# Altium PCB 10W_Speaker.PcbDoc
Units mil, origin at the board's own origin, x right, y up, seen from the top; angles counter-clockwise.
Board outline 4298.07 x 4067.91 mil, 4 copper layers (Top Layer, Internal Plane 2, Internal Plane 1, Bottom Layer), stack 30.634 mil thick; 46 components, 34 nets, 134 pads, 44 vias.
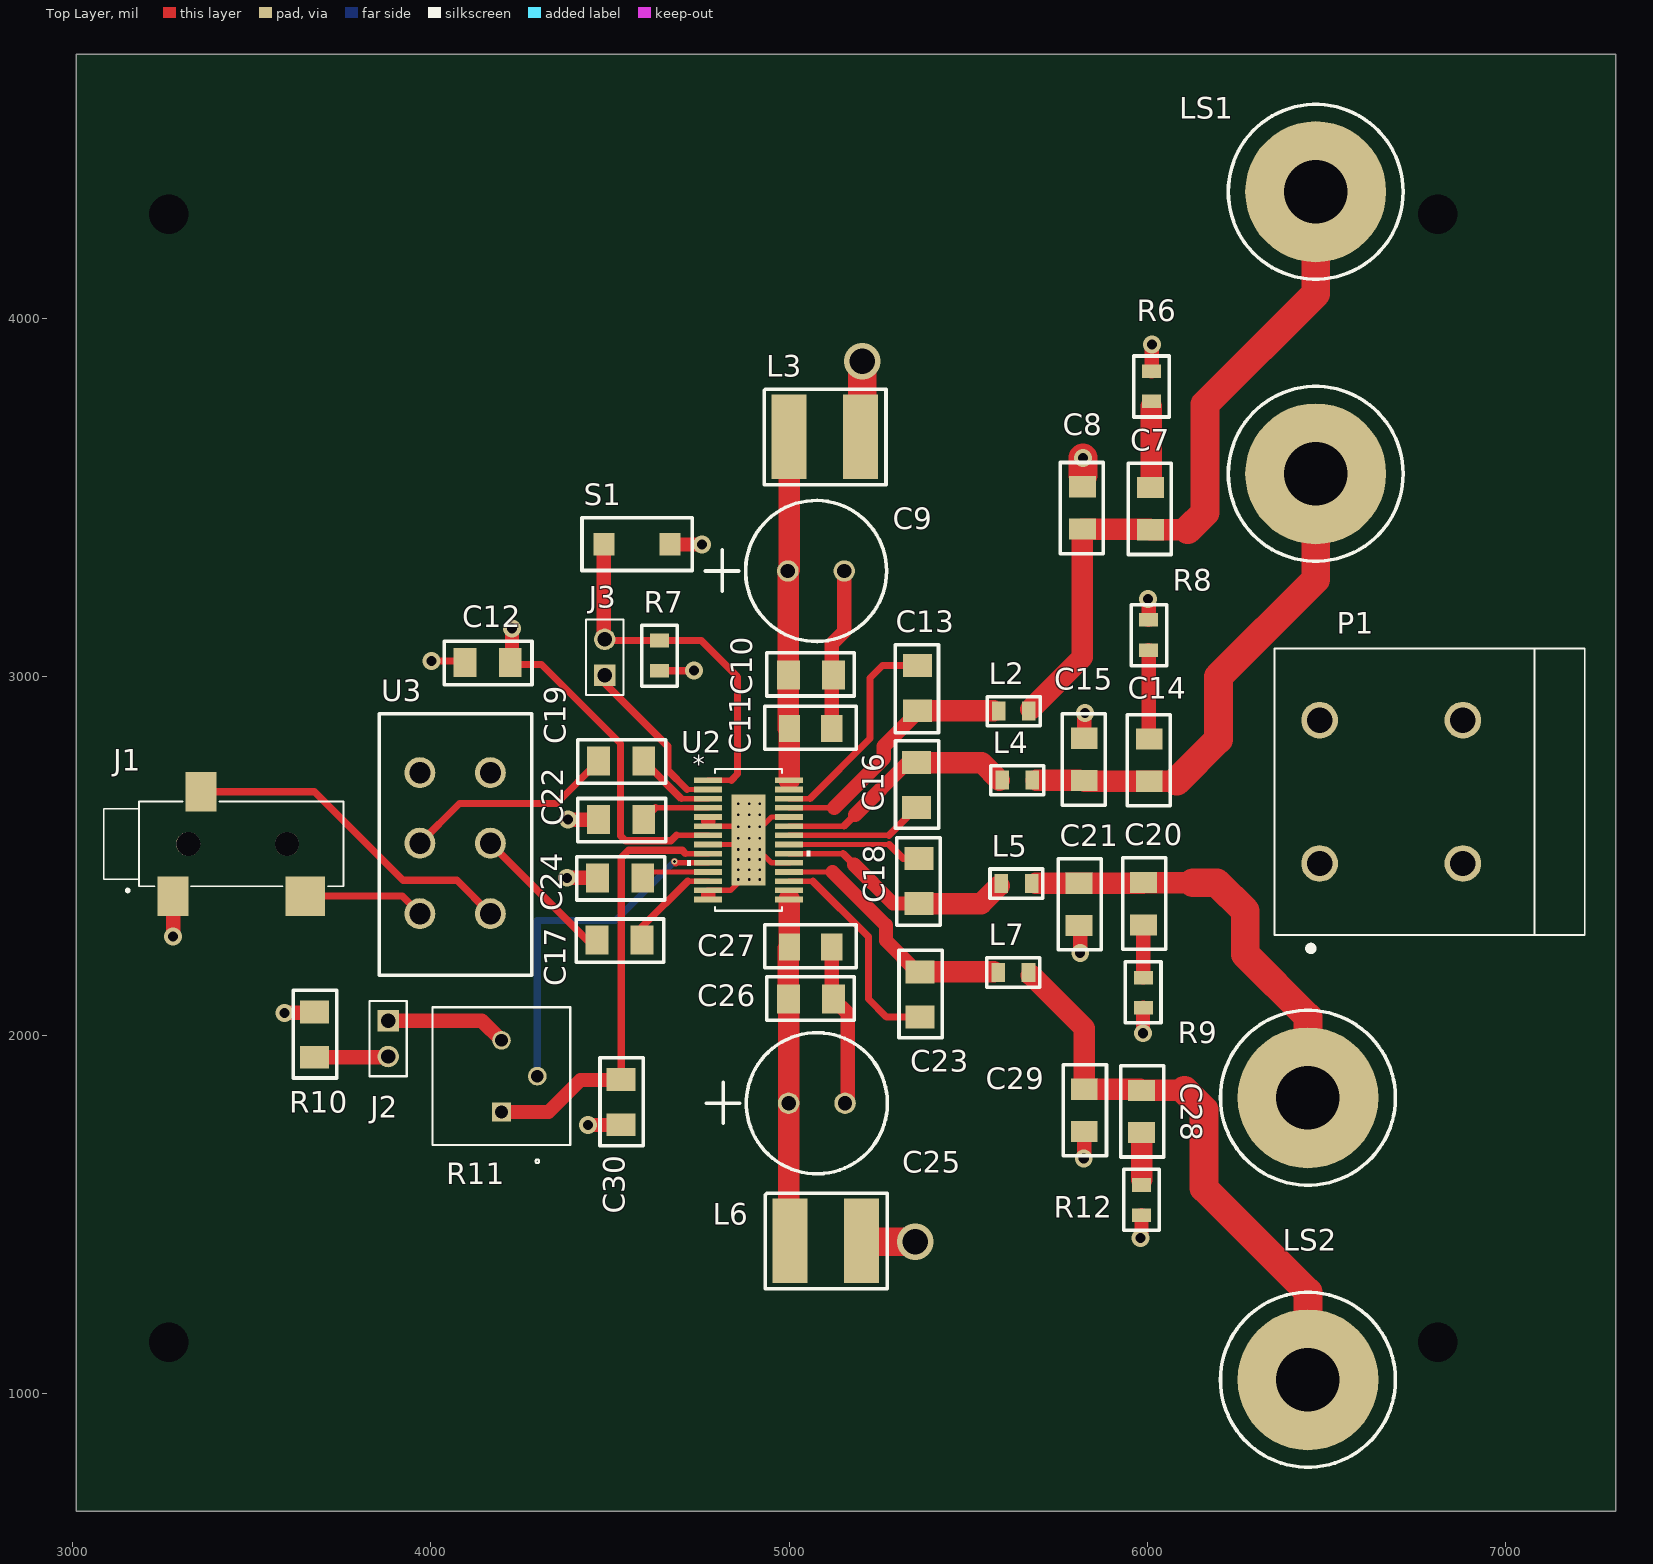
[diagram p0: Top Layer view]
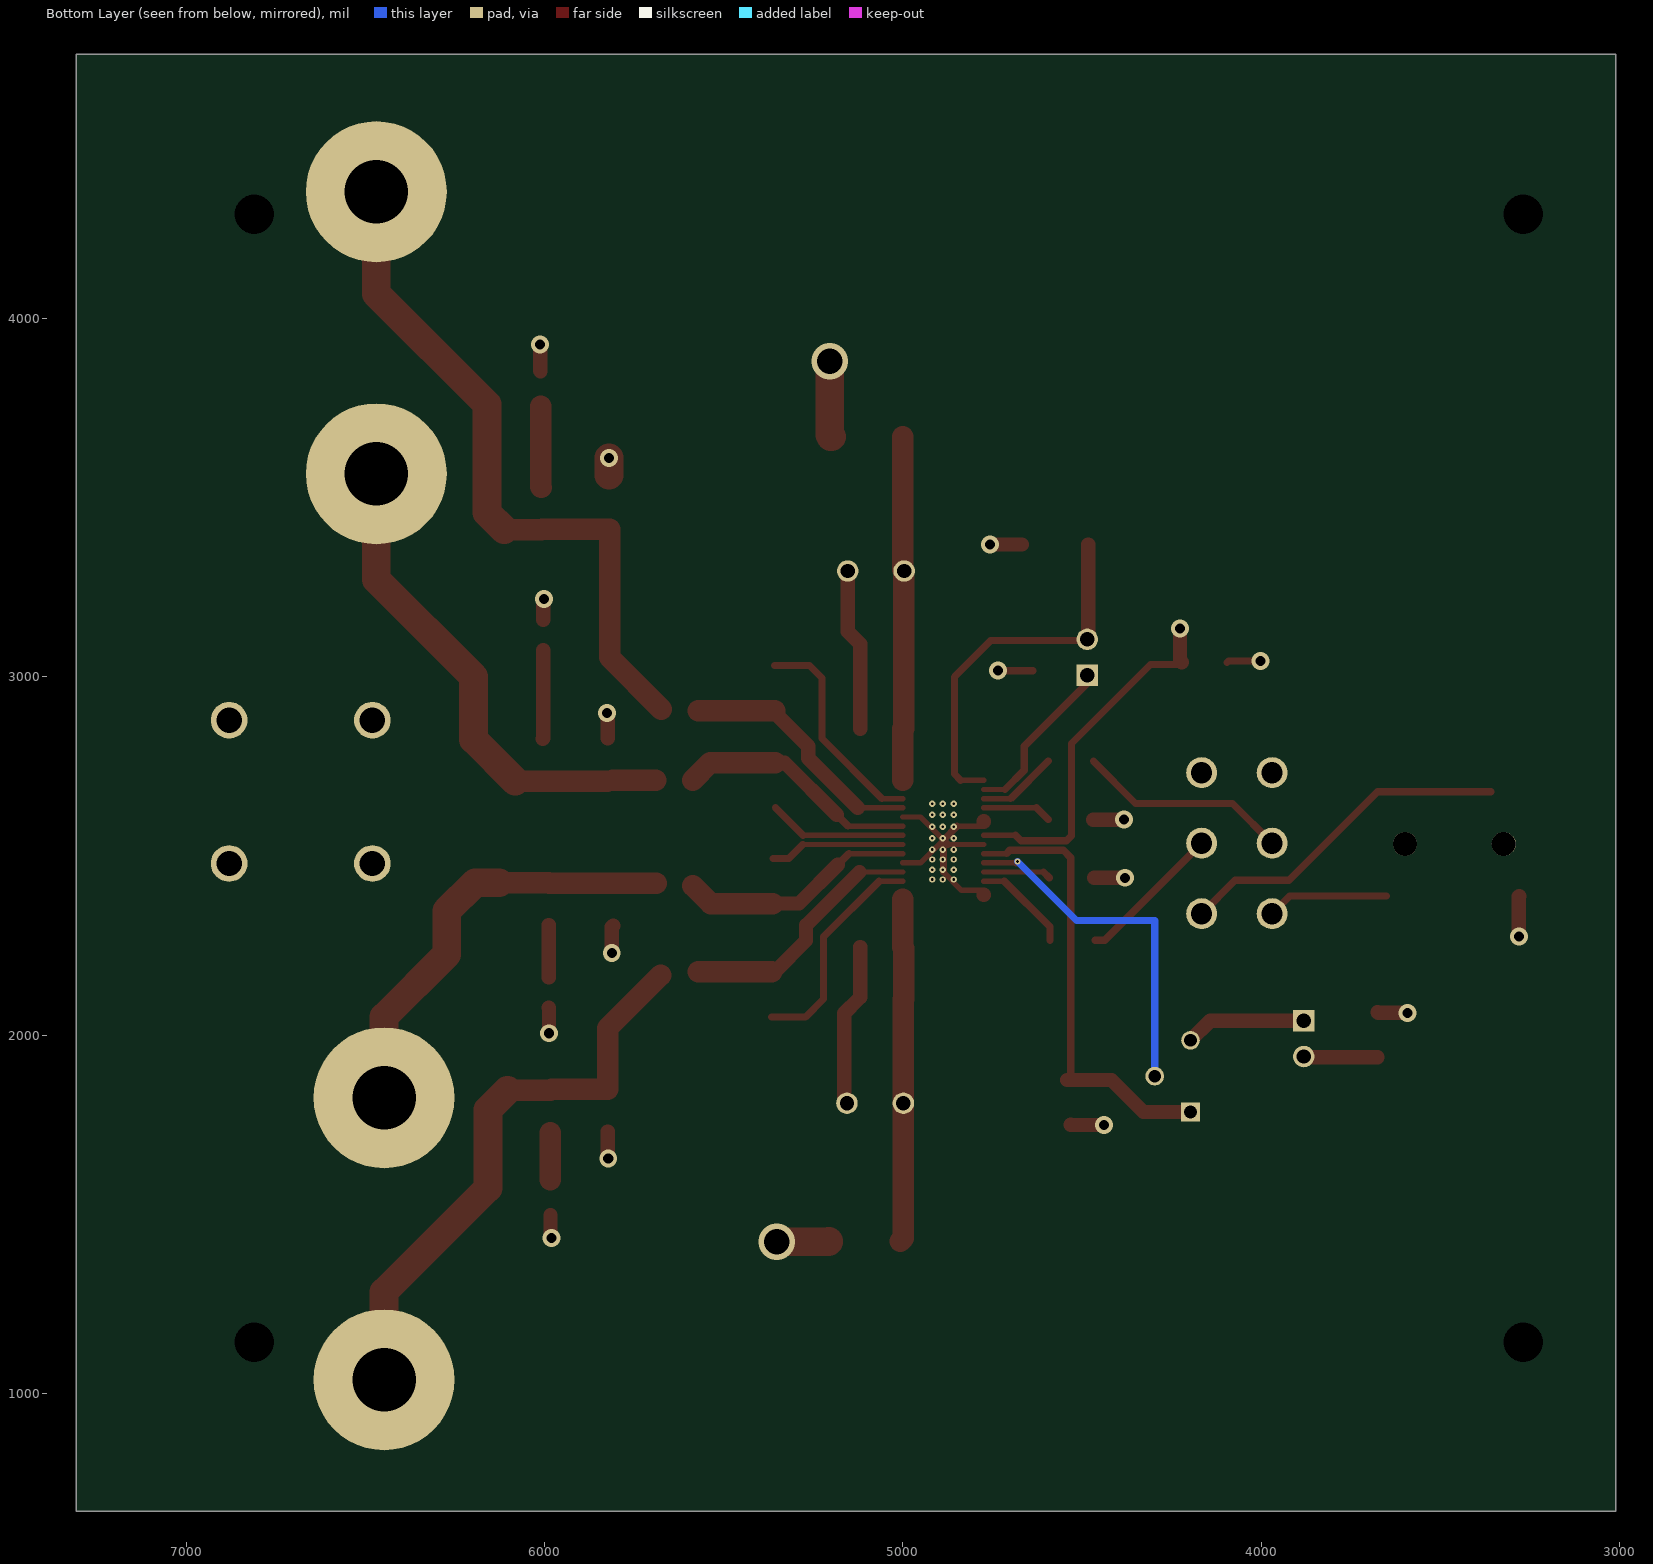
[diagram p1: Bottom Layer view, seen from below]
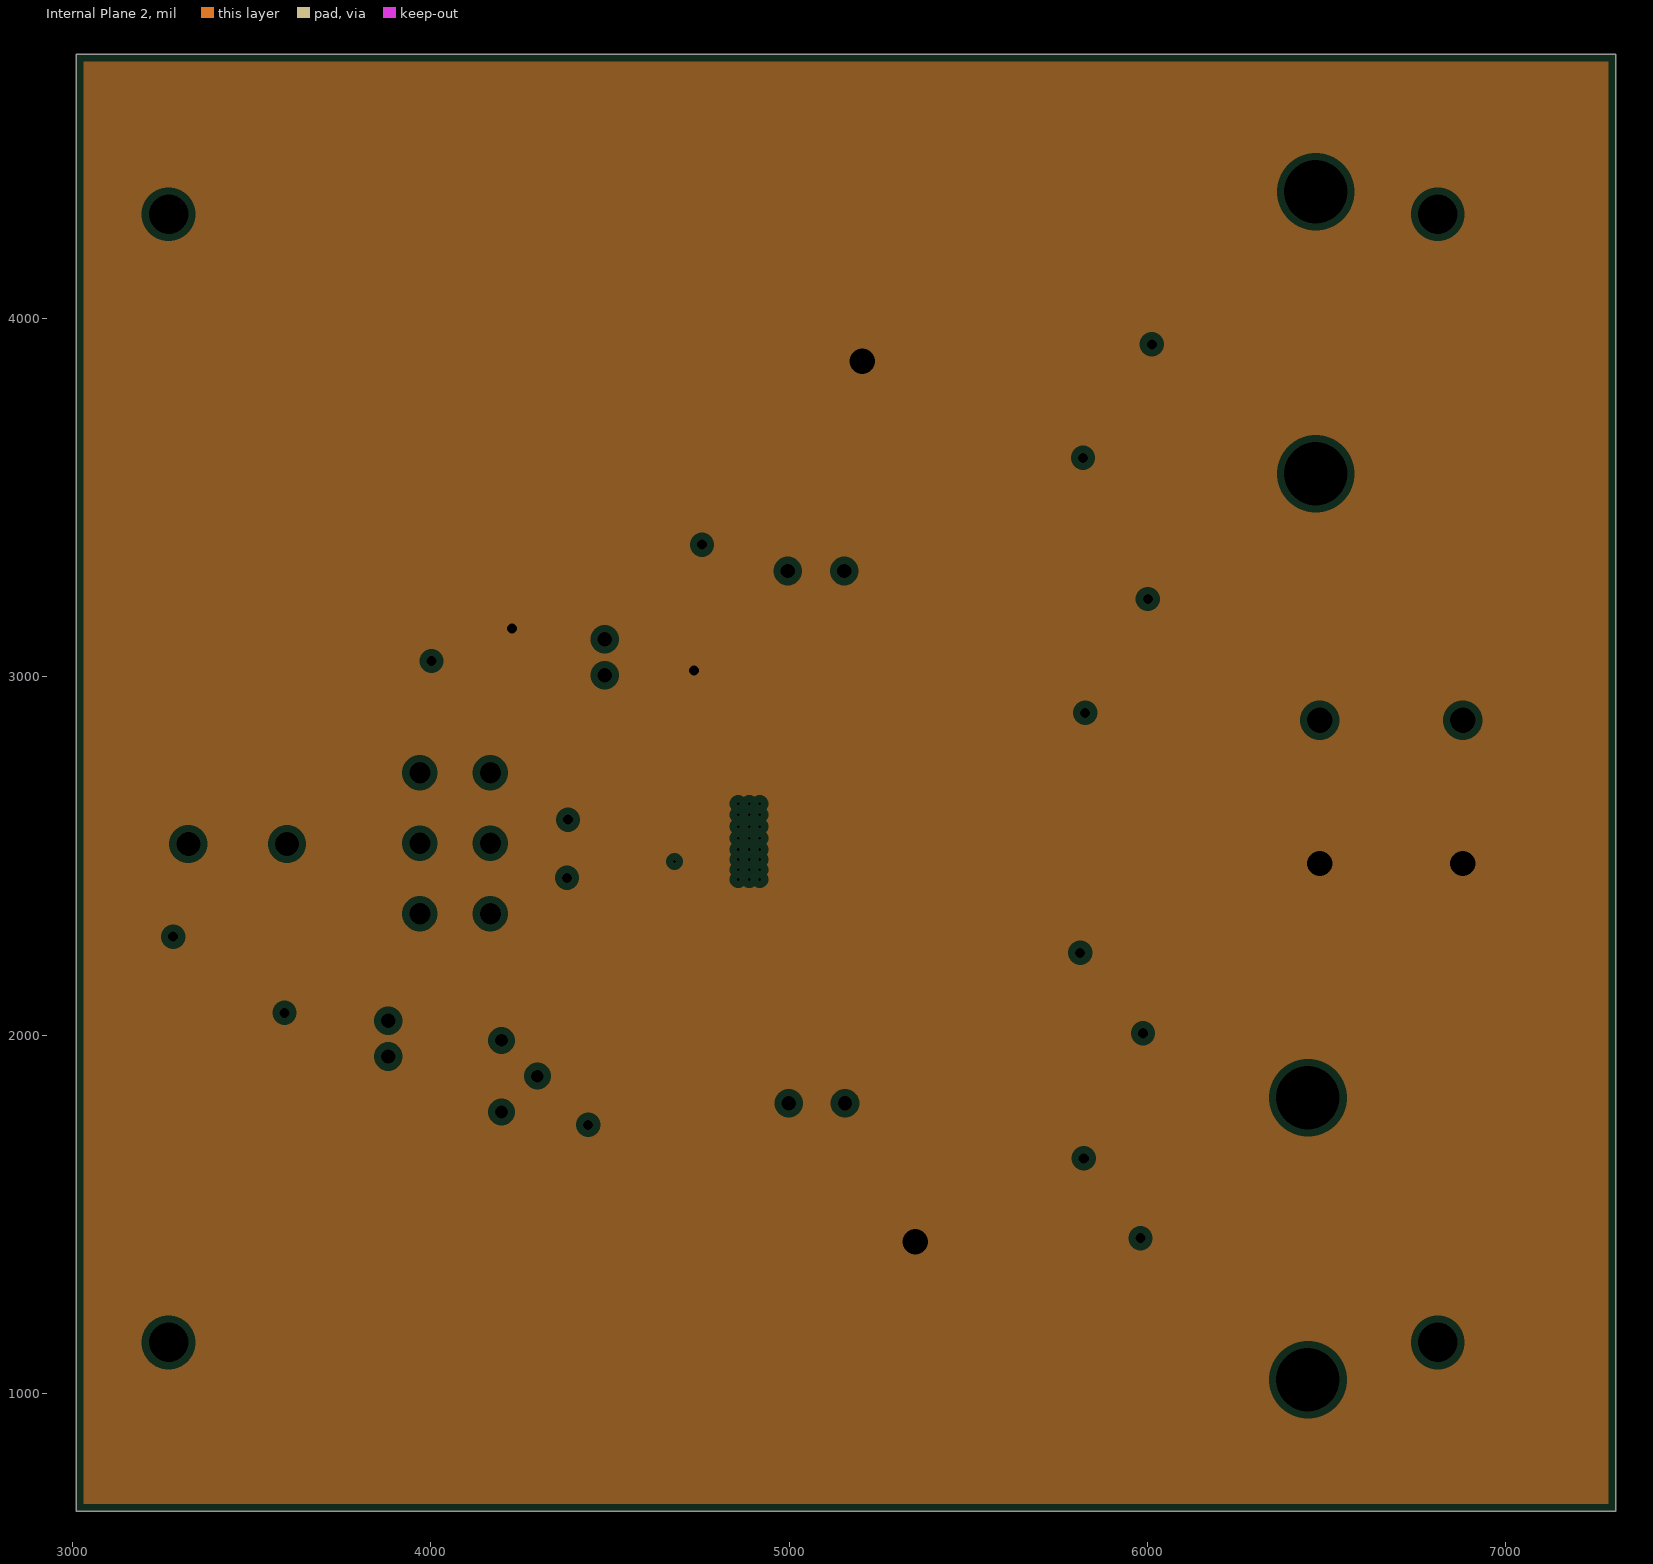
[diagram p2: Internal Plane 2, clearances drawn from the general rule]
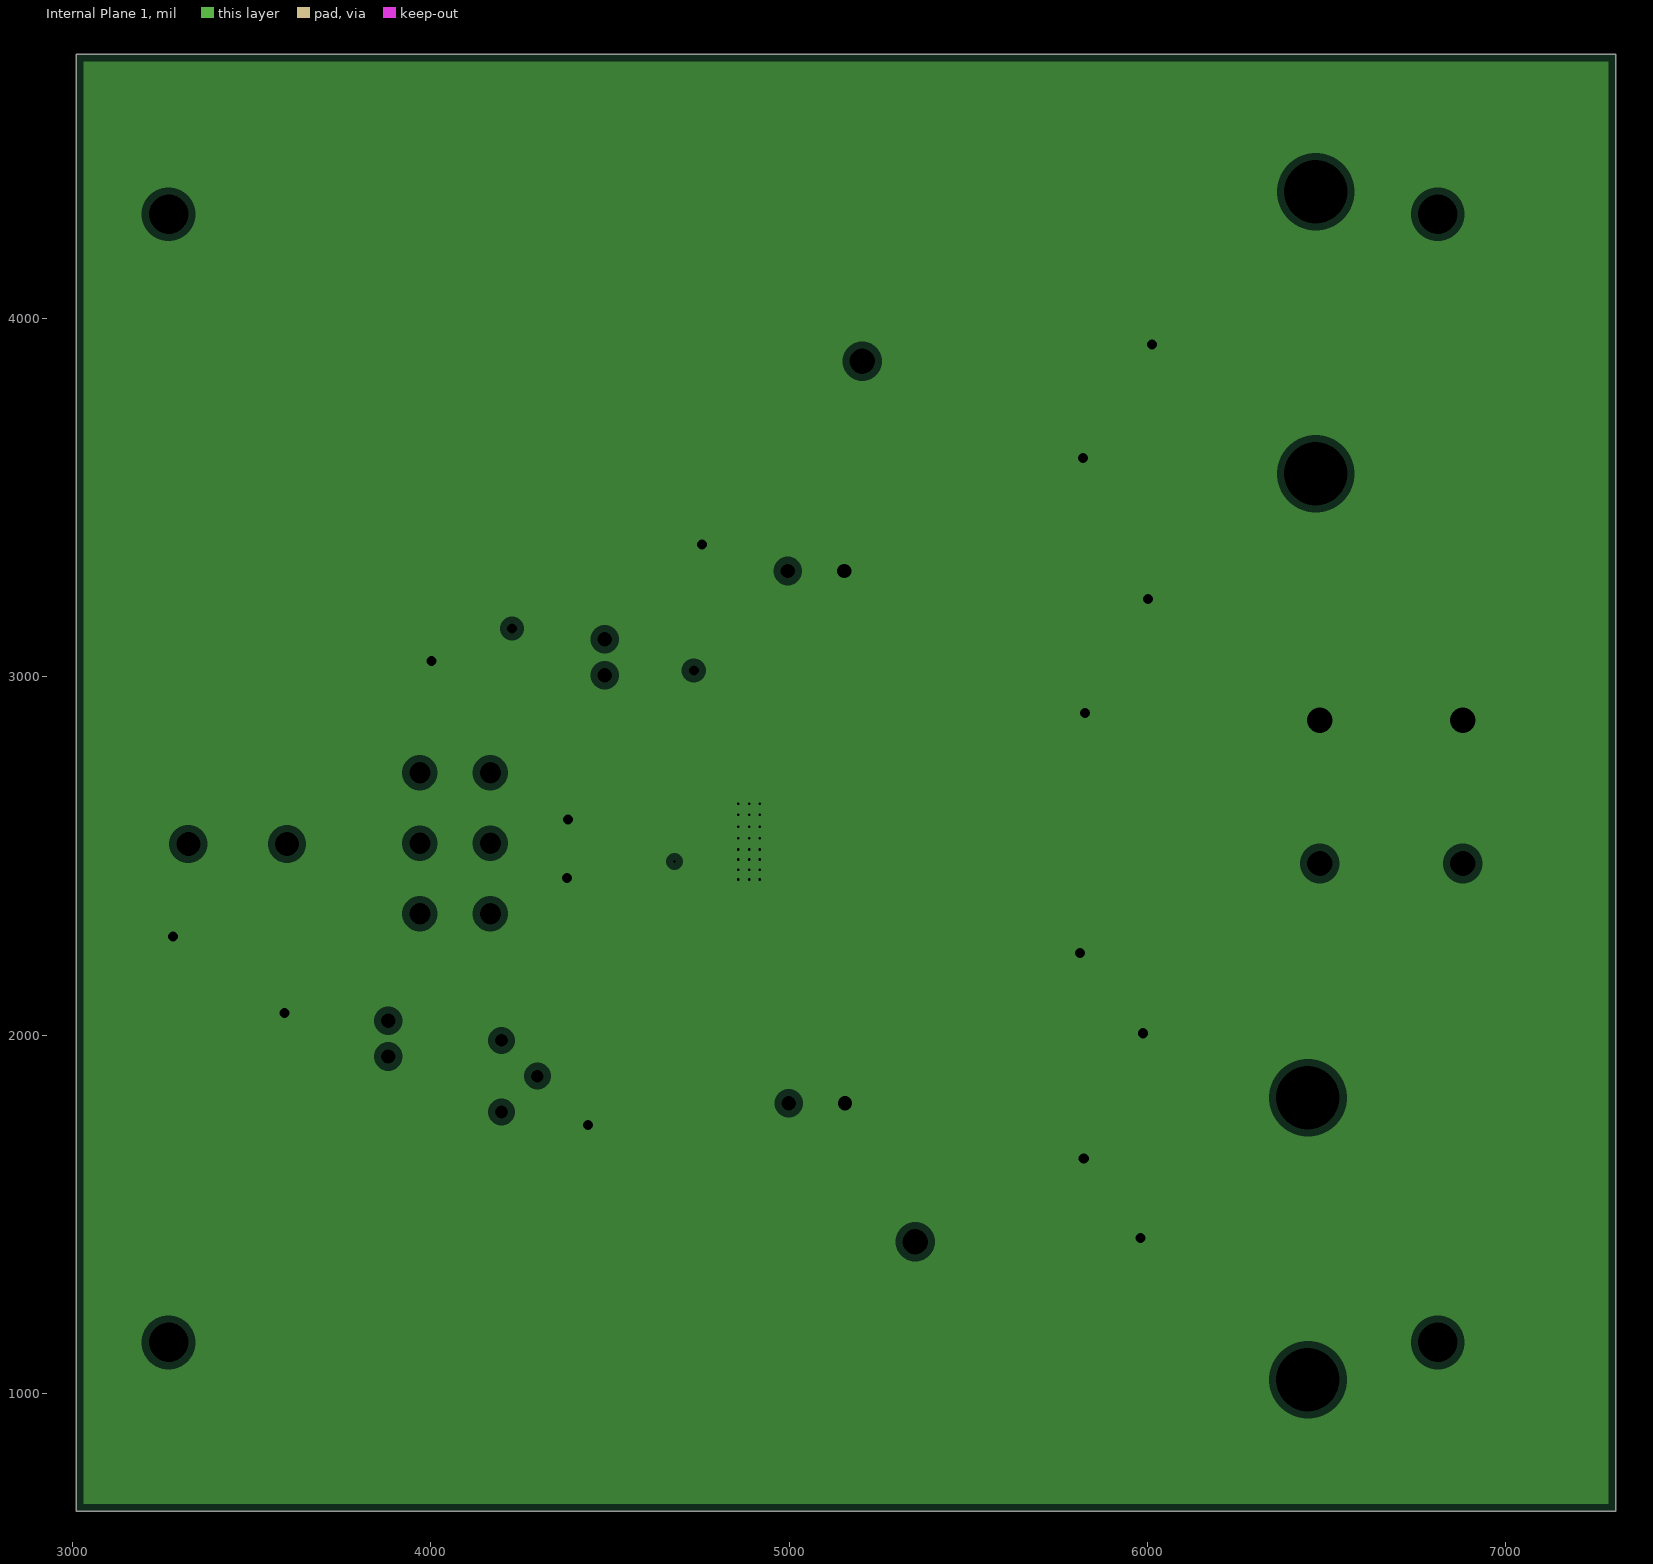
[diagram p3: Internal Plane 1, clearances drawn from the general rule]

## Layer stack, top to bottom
Top Solder: solder mask 0.4, Solder Resist, Dk 3.5
Top Layer: signal copper 1.4
Dielectric 1: core 10, FR-4, Dk 4.2
Internal Plane 2: plane copper 1.417, net VCC
Dielectric 3: prepreg 5, Dk 4.2
Internal Plane 1: plane copper 1.417, net GND
Dielectric 2: core 10, Dk 4.2
Bottom Layer: signal copper 1.4
Bottom Solder: solder mask 0.4, Solder Resist, Dk 3.5

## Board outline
3010,670.28 7308.07,670.28 7308.07,4738.19 3010,4738.19

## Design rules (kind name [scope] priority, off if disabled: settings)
BoardOutlineClearance [All] p1: gap=39.37 ignorepadtopadclearanceinfootprint=FALSE
Clearance [All] p1: gap=5 ignorepadtopadclearanceinfootprint=TRUE
HoleSize [All] p1: absolutevalues=TRUE maxlimit=248.03 minlimit=7.87 maxpercent=80.000 minpercent=20.000
MinimumSolderMaskSliver [All] p1: minsoldermaskwidth=5
PlaneClearance [All] p1: clearance=20
PlaneConnect [All] p1: planeconnectstyle=Direct reliefexpansion=20 reliefentries=4 reliefconductorwidth=10 reliefairgap=10
PolygonConnect [All] p1: connectstyle=Relief reliefconductorwidth=10 reliefentries=4 polygonreliefangle="90 Angle" airgapwidth=10
RoutingVias [All] p1: holewidth=28 width=50 viastyle="Through Hole" minholewidth=28 minwidth=50 maxholewidth=28 maxwidth=50
SilkToSilkClearance [All] p1: silktosilkclearance=5
SilkToSolderMaskClearance [IsPad] p1: minsilkscreentomaskgap=5 clearancetoexposedcopper=TRUE
SolderMaskExpansion [All] p1: expansion=4
Width [All] p1: maxlimit=100 minlimit=15 preferedwidth=15
24 further rules are at their usual default settings.

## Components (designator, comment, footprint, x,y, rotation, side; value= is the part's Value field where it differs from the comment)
C7 "1000pF" "1000pF (1206 case)" 6009.21,3528.62 r270 top
C8 "1000pF" "1000pF (1206 case)" 5819.21,3530.51 r270 top
C9 "100uF" "100uF electrolytic cap" 5154.21,3295.51 r180 top
C10 "0.1uF" "0.1uF (1206 case)" 5124.21,3005.51 r180 top value=0.22uF
C11 "1000pF" "1000pF (1206 case)" 5119.21,2855.51 r180 top
C12 "1uF" "1uF (1206 case)" 4095.47,3040.35 r0 top value=0.22uF
C13 "0.22uF" "0.22uF (1206 case)" 5358.27,3031.5 r270 top
C14 "1000pF" "1000pF (1206 case)" 6005.91,2826.77 r270 top
C15 "1000pF" "1000pF (1206 case)" 5824.21,2828.62 r270 top
C16 "0.22uF" "0.22uF (1206 case)" 5356.3,2634.84 r90 top
C17 "1uF" "1uF (1206 case)" 4463.58,2264.76 r0 top value=0.22uF
C18 "0.22uF" "0.22uF (1206 case)" 5363.19,2493.11 r270 top
C19 "1uF" "1uF (1206 case)" 4468.5,2764.76 r0 top value=0.22uF
C20 "1000pF" "1000pF (1206 case)" 5989.21,2307.4 r90 top
C21 "1000pF" "1000pF (1206 case)" 5809.21,2305.51 r90 top
C22 "1uF" "1uF (1206 case)" 4468.5,2601.38 r0 top value=0.22uF
C23 "0.22uF" "0.22uF (1206 case)" 5366.14,2050.2 r90 top
C24 "1uF" "1uF (1206 case)" 4465.55,2438.98 r0 top value=0.22uF
C25 "100uF" "100uF electrolytic cap" 5156.34,1809.53 r180 top
C26 "0.1uF" "0.1uF (1206 case)" 5124.21,2100.51 r180 top value=0.22uF
C27 "1000pF" "1000pF (1206 case)" 5119.21,2245.51 r180 top
C28 "1000pF" "1000pF (1206 case)" 5984.21,1727.4 r90 top
C29 "1000pF" "1000pF (1206 case)" 5824.21,1730.51 r90 top
C30 "1uF" "1uF (1206 case)" 4531.18,1749.45 r90 top value=0.22uF
J1 "SJ-3523-SMT-TR" "Audio Jack 3.5mm" 3322.83,2533.46 r0 top
J2 "Part Number: 77311-118-02LF" Jumper 3880.91,1939.88 r90 top value=Value
J3 "Part Number: 77311-118-02LF" Jumper 4485.47,3104.72 r270 top value=Value
L2 "300Ohms" "300 Ohms Ferrite Bead (0805 case)" 5630.91,2904.53 r180 top
L3 "100Ohms" "100 ohms ferrite" 5049.21,3670.51 r0 top value=300Ohms
L4 "300Ohms" "300 Ohms Ferrite Bead (0805 case)" 5640.75,2711.61 r180 top
L5 "300Ohms" "300 Ohms Ferrite Bead (0805 case)" 5638.78,2423.23 r180 top
L6 "100Ohms" "100 ohms ferrite" 5052.17,1425.2 r0 top value=300Ohms
L7 "300Ohms" "300 Ohms Ferrite Bead (0805 case)" 5629.92,2175.2 r180 top
LS1 "Speaker" "Banana Plug" 6470.47,4354.33 r270 top
LS2 "Speaker" "Banana Plug" 6448.82,1824.8 r270 top
P1 "Connector" Connector 6681.3,2678.94 r90 top
R6 "68 Ohms" "68 Ohms (0805 case)" 6011.81,3814.96 r270 top value=Value
R7 "100K" "100K Ohms (0805 case)" 4637.8,3062.88 r270 top value=Value
R8 "68 Ohms" "68 Ohms (0805 case)" 6004.21,3120.51 r270 top value=Value
R9 "68 Ohms" "68 Ohms (0805 case)" 5989.17,2114.57 r90 top value=Value
R10 "10k" "0.22uF (1206 case)" 3675.2,1937.99 r90 top value=Value
R11 "100k pot" "100k trimmer" 4196.2,1985.12 r90 top value=Value
R12 "68 Ohms" "68 Ohms (0805 case)" 5984.21,1535.51 r90 top value=Value
S1 "SW-PB" "E switch" 4575.47,3369.72 r0 top
U2 "Part Number: TPA3136D2PWPR" TPA3136_PWP28_2p4X3.4-M 4887.21,2544.76 r0 top value=Value
U3 "2channel 50k pot" "50K Ohms Carbon Log" 3969.21,2732.36 r270 top

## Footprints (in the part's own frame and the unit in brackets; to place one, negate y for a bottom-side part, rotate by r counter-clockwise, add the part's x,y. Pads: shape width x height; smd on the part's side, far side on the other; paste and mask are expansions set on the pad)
"0.1uF (1206 case)" [mm]
  rect 1.62x2.06 smd: 1(0,0) 2(3.2,0)
  silkscreen extent -1.48,-1.58 4.75,1.5
"0.22uF (1206 case)" [mm]
  rect 1.62x2.06 smd: 1(0,0) 2(3.2,0)
  silkscreen extent -1.48,-1.58 4.75,1.5
"1uF (1206 case)" [mm]
  rect 1.62x2.06 smd: 1(0,0) 2(3.2,0)
  silkscreen extent -1.48,-1.58 4.75,1.5
"50K Ohms Carbon Log" [mm]
  round 2.2 hole 1.5: 1(0,0) 2(5,0) 3(10,0) 4(0,5) 5(5,5) 6(10,5)
  silkscreen extent -4.18,-2.88 14.35,7.93
"68 Ohms (0805 case)" [mil] "STA_RMCF0805"
  rect 37.99x53 smd: 1(-38.5,0) 2(45.87,0)
  silkscreen extent -81,-49 90,50
"100 ohms ferrite" [mm]
  rect 2.5x6 smd: 1(-1.25,0) 2(3.82,0)
  silkscreen extent -3,-3.4 5.63,3.37
"100K Ohms (0805 case)" [mil] "0805 case"
  rect 37.99x53 smd: 1(-38.5,0) 2(45.87,0)
  silkscreen extent -81,-49 90,50
"100k trimmer" [mil]
  rect 52x52 hole 35.43 mask+0: 1(-200,-1)
  round 52 hole 35.43 mask+0: 2(-100,-101) 3(0,-1)
  silkscreen extent -342,-193 93,192, body extent 0,0 10,10, height 10
"100uF electrolytic cap" [mil] "electrolytic cap"
  round 60 hole 40: 1(157.48,0) 2(0,0)
  silkscreen extent -118,-197 388,197
"300 Ohms Ferrite Bead (0805 case)" [mil]
  rect 37.99x53 smd: 1(-38.5,0) 2(45.87,0)
  silkscreen extent -70,-40 78,41
"1000pF (1206 case)" [mm]
  rect 1.5x1.9 smd: 1(0,0) 2(3,0)
  silkscreen extent -1.73,-1.58 4.75,1.48
"Audio Jack 3.5mm" [mm]
  rect 2.2x2.8 smd: 1(-1.1,-3.7) 3(0.9,3.7)
  rect 2.8x2.8 smd: 2(8.3,-3.7)
  round 1.7 hole 1.7 unplated: None(0,0) None(7,0)
  silkscreen extent -6,-3.4 11,3
"Banana Plug" [mm]
  round 10 hole 4.5: 1(0,0) 2(20,0)
  silkscreen extent -6.2,-6.2 26.2,6.2
Connector [mm]
  round 2.6 hole 1.8: 1.1(-5.08,5.08) 1.2(-5.08,-5.08) 2.1(5.08,5.08) 2.2(5.08,-5.08)
  silkscreen extent -11.3,-13.72 10.16,8.28
"E switch" [mm]
  rect 1.5x1.6 smd: 1(-2.35,0) 2(2.35,0)
  silkscreen extent -3.9,-1.85 3.93,1.9
Jumper [mil]
  rect 60x60 hole 40: 1(100,0)
  round 60 hole 40: 2(0,0)
  silkscreen extent -55,-52 155,52
TPA3136_PWP28_2p4X3.4-M [mil]
  rect 78x16 smd paste+0 mask+0: 1(-113,166.34) 2(-113,140.75) 3(-113,115.16) 4(-113,89.57) 5(-113,63.98) 6(-113,38.39) 7(-113,12.8) 8(-113,-12.8) 9(-113,-38.39) 10(-113,-63.98) 11(-113,-89.57) 12(-113,-115.16) 13(-113,-140.75) 14(-113,-166.34) 15(113,-166.34) 16(113,-140.75) 17(113,-115.16) 18(113,-89.57) 19(113,-63.98) 20(113,-38.39) 21(113,-12.8) 22(113,12.8) 23(113,38.39) 24(113,63.98) 25(113,89.57) 26(113,115.16) 27(113,140.75) 28(113,166.34)
  rect 95x254.33 smd paste-78.5 mask+0: EPAD(0,0)
  silkscreen extent -172,-198 172,198

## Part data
C7 C8 C10 C11 C12 C13 C14 C15 C16 C17 C18 C19 C20 C21 C22 C23 C24 C26 C27 C28 C29 C30: library part "Cap Semi", "Capacitor (Semiconductor SIM Model)"
C9: library part "Cap Pol1"
C25: library part "Cap Pol1", "Polarized Capacitor (Radial)"
J1: "3.5 mm, Stereo, Right Angle, Surface Mount _SMT_, Audio Jack Connector", Package="LGA-10 STMicroelectronics"
J2 J3: library part 77311-118-02LF, "No Description Available"
L2 L3 L4 L5 L6 L7: library part "300 Ohms Ferriter Bead", "No Description Available"
LS1 LS2: "Loudspeaker"
P1: library part 1929517, "Conn Terminal Block 2 POS 10.16mm Solder ST Thru-Hole 57A", Package=None
R6 R8 R9 R10 R12: library part RMCF0805FT68R0, "No Description Available"
R7: library part RMCF0805FT100K, "No Description Available"
R11: library part 3386P-1-104LF, "No Description Available"
S1: "Switch"
U2: library part TPA3136D2PWPR, "No Description Available"

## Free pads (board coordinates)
  round 0 on Mech16 paste+0 mask+0: 1(4235,4715)
  round 0 hole 110.24: 3(3267.72,1141.73) 3(3267.72,4291.34) 3(6811.02,1141.73) 3(6811.02,4291.34)

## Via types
v1: diameter 17.72, hole 7.87, Top Layer to Bottom Layer, tented both sides, 24 vias
v2: diameter 50, hole 28, Top Layer to Bottom Layer, 17 vias
v3: diameter 102.36, hole 70.87, Top Layer to Bottom Layer, 2 vias
v4: diameter 17.72, hole 7.87, Top Layer to Bottom Layer, 1 vias

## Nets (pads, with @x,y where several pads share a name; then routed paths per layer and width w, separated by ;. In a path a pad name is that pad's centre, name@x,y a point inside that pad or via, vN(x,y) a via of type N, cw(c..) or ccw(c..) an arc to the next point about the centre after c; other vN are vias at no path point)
\F\A\U\L\T\: J3.1 U2.2 | length 473.5
  Top Layer w15: 4715.08,2685.51 U2.2
  Top Layer w20: J3.1 4485.47,2982.05 4661.42,2806.1 4661.42,2739.17 4715.08,2685.51
\S\D\: J3.2 R7.1 S1.1 U2.1 | length 1042.3
  Top Layer w15: U2.1 4839.06,2711.1
  Top Layer w20: J3.2@4482.95,3101.38 R7.1 4754.92,3101.38 4856.3,3000 4856.3,2728.35 4839.06,2711.1
  Top Layer w40: S1.1 4482.95,3107.24 J3.2
GND: C8.1 C9.2 C10.1 C11.1 C12.1 C15.1 C21.1 C22.1 C24.1 C25.2 C26.1 C27.1 C29.1 C30.1 J1.1 P1.2.1 P1.2.2 R6.1 R8.1 R9.1 R10.2 R12.1 S1.2 U2.5 U2.6 U2.8 U2.13 U2.14 U2.19 U2.24 U2.EPAD | length 2848.9
  Top Layer w15: U2.13 4836.1,2404.02 U2.EPAD@4887.21,2455.13 ; U2.8 U2.EPAD@4874.42,2531.97 ; U2.6 U2.EPAD@4848.83,2583.15 ; U2.19 4951.19,2480.79 U2.EPAD 4951.19,2608.74 U2.24
  Top Layer w20: v2(4001.97,3044.29) 4091.54,3044.29 C12.1 ; U2.EPAD@4848.83,2583.15 U2.EPAD@4885.77,2546.2 ; U2.EPAD@4874.42,2531.97 U2.EPAD 4887.21,2490.16 U2.EPAD@4887.21,2455.13
  Top Layer w40: J1.1 3280.51,2386.81 v2(3280.51,2274.61) ; v2(3591.54,2062.01) 3673.23,2062.01 R10.2 ; v2(4379.92,2438.98) C24.1 ; v2(4382.87,2601.38) C22.1 ; v2(4438.98,1749.02) 4530.75,1749.02 C30.1 ; S1.2 4756.26,3369.72 v2(4756.89,3369.09) ; 4774.21,2390.75 4774.21,2391.73 ; 4774.21,2595.47 4774.21,2596.46 ; C27.1 5119.21,2105.51 C26.1 5164.21,2060.51 C25.2@5164.21,1810.51 ; C11.1 5119.21,3091.65 5154.21,3126.65 C9.2 ; C21.1 5812.99,2301.73 v2(5812.99,2229.33) ; v2(5822.83,1655.51) 5824.21,1656.89 C29.1 ; C15.1 5824.21,2897.05 v2(5826.77,2899.61) ; v2(5981.3,1433.07) 5984.21,1435.98 R12.1 ; v2(5988.19,2004.92) 5988.19,2075.08 R9.1 ; v2(6001.97,3217.52) 6004.21,3215.28 R8.1 ; R6.1 6012.8,3854.44 v2(6012.8,3928.15)
  Top Layer w80: 5820.87,3562.99 v2(5820.87,3611.22)
  other v1: 4858.27,2434.06 4888.78,2434.06 4918.31,2434.06 4858.27,2461.61 4888.78,2461.61 4918.31,2461.61 4858.27,2490.16 4888.78,2490.16 4918.31,2490.16 4858.27,2517.72 4888.78,2517.72 4918.31,2517.72 4858.27,2549.21 4888.78,2549.21 4918.31,2549.21 4858.27,2581.69 4888.78,2581.69 4918.31,2581.69 4858.27,2615.16 4888.78,2615.16 4918.31,2615.16 4858.27,2645.67 4888.78,2645.67 4918.31,2645.67
LINN: C22.2 U2.4 | length 193.4
  Top Layer w15: 4627.44,2634.33 U2.4
  Top Layer w20: C22.2 4627.44,2634.33
LINP: C19.2 U2.3 | length 223.2
  Top Layer w15: 4699.33,2659.92 U2.3
  Top Layer w20: C19.2 4699.33,2659.92
NetC7_1: C7.1 R6.2 | length 227.4
  Top Layer w60: C7.1 6011.81,3531.22 R6.2@6011.81,3754.92
NetC7_2: C7.2 C8.2 L2.1 LS1.1 | length 1949
  Top Layer w15: C7.2@6007.32,3412.4 C7.2
  Top Layer w60: L2.1@5674.76,2909.88 5819.21,3054.33 C8.2 C7.2@6007.32,3412.4 ; C7.2 6113.27,3410.51
  Top Layer w80: 6113.27,3410.51 6161.42,3458.66 6161.42,3760.83 6470.47,4069.88 LS1.1
NetC13_1: C13.1 U2.26 | length 611.1
  Top Layer w15: U2.26 5058.54,2659.92
  Top Layer w20: 5058.54,2659.92 5226.38,2827.76 5226.38,2997.05 5260.83,3031.5 C13.1
NetC14_1: C14.1 R8.2 | length 248.6
  Top Layer w40: R8.2 6004.21,2828.46 C14.1
NetC14_2: C14.2 C15.2 L4.1 LS1.2 | length 1415.3
  Top Layer w40: C15.2@5809.57,2711.61 5817.44,2703.74 C15.2@5825.2,2708.54
  Top Layer w60: L4.1@5689.96,2711.61 C15.2@5809.57,2711.61 ; C15.2@5825.2,2708.54 C14.2@6005.2,2708.54 ; C14.2 6082.36,2708.66
  Top Layer w80: 6082.36,2708.66 6198.82,2825.12 6198.82,3000 6470.47,3271.65 LS1.2
NetC16_1: C16.1 U2.22 | length 388.1
  Top Layer w15: U2.22 5279.02,2557.56
  Top Layer w20: 5279.02,2557.56 C16.1
NetC17_1: C17.1 U3.5 | length 409.7
  Top Layer w20: U3.5 4436.81,2264.76 C17.1
NetC18_1: C18.1 U2.21 | length 379.1
  Top Layer w15: U2.21 5280,2531.97
  Top Layer w20: 5280,2531.97 5318.86,2493.11 C18.1
NetC19_1: C19.1 U3.2 | length 595.9
  Top Layer w20: U3.2@3967.6,2535.51 U3.2 4080.35,2646.65 4350.39,2646.65 C19.1
NetC20_1: C20.1 R9.2 | length 147
  Top Layer w40: R9.2 5989.21,2160.47 C20.1
NetC20_2: C20.2 C21.2 L5.1 LS2.1 | length 1212.6
  Top Layer w40: C21.2@5808.82,2423.23 C21.2 ; C20.2@5987.32,2423.62 C20.2
  Top Layer w60: L5.1@5688.98,2423.23 C21.2@5808.82,2423.23 ; C21.2 C20.2@5987.32,2423.62 ; C20.2 6127.64,2425.51
  Top Layer w80: 6127.64,2425.51 6194.57,2425.51 6273.62,2346.46 6273.62,2225.39 6448.82,2050.2 LS2.1
NetC23_1: C23.1 U2.17 | length 625.1
  Top Layer w15: U2.17 5066.46,2429.61
  Top Layer w20: 5066.46,2429.61 5221.46,2274.61 5221.46,2100.39 5271.65,2050.2 C23.1
NetC28_1: C28.1 R12.2 | length 131.9
  Top Layer w60: R12.2@5984.21,1595.47 C28.1
NetC28_2: C28.2 C29.2 L7.1 LS2.2 | length 1611.5
  Top Layer w40: C28.2@5981.1,1848.62 C28.2
  Top Layer w60: L7.1@5676.73,2166.89 5824.21,2019.41 C29.2 C28.2@5981.1,1848.62 ; C28.2 6104.21,1845.51
  Top Layer w80: 6104.21,1845.51 6158.46,1791.26 6158.46,1572.83 6448.82,1282.48 LS2.2
NetC30_2: C30.2 R11.1 U2.9 | length 1260.6
  Top Layer w15: 4711.14,2506.38 U2.9
  Top Layer w20: C30.2@4541.02,1874.45 4531.5,1883.98 4531.5,2495.08 4552.17,2515.75 4701.77,2515.75 4711.14,2506.38
  Top Layer w40: R11.1 4328.43,1785.12 4417.76,1874.45 C30.2@4541.02,1874.45
NetJ1_2: J1.2 U3.3 | length 340
  Top Layer w20: J1.2 3920.08,2387.8 U3.3
NetJ1_3: J1.3 U3.6 | length 948.8
  Top Layer w20: J1.3 3675.2,2679.13 3922.24,2432.09 4072.64,2432.09 U3.6
NetJ2_A1: J2.2 R10.1 | length 206.5
  Top Layer w40: R10.1 3879.02,1937.99 J2.2
NetJ2_A2: J2.1 R11.3 | length 339
  Top Layer w40: J2.1 4142.44,2039.88 R11.3
OUTNL: C16.2 L4.2 U2.23 | length 680.8
  Top Layer w15: U2.23 5153.03,2583.15
  Top Layer w20: 5153.03,2583.15 5185.04,2615.16
  Top Layer w40: 5185.04,2615.16 5330.71,2760.83 C16.2
  Top Layer w60: C16.2 5537.8,2760.83 L4.2@5587.01,2711.61
OUTNR: C18.2 L5.2 U2.20 | length 664.3
  Top Layer w15: U2.20 5151.1,2506.38
  Top Layer w20: 5151.1,2506.38 5182.09,2475.39
  Top Layer w40: 5182.09,2475.39 5290.35,2367.13 C18.2
  Top Layer w60: C18.2 5536.81,2367.13 L5.2@5586.32,2416.63
OUTPL: C13.2 L2.2 U2.25 | length 706
  Top Layer w15: U2.25 5126.46,2634.33
  Top Layer w20: C13.2@5358.27,2899.61 C13.2
  Top Layer w40: 5126.46,2634.33 5264.76,2772.64 5264.76,2806.1 C13.2@5358.27,2899.61
  Top Layer w60: C13.2 L2.2@5570.87,2905.51
OUTPR: C23.2 L7.2 U2.18 | length 711
  Top Layer w15: U2.18 5121.54,2455.2
  Top Layer w20: C23.2@5358.27,2176.18 C23.2
  Top Layer w40: 5121.54,2455.2 5270.67,2306.06 5270.67,2263.78 C23.2@5358.27,2176.18
  Top Layer w60: C23.2 L7.2@5570.87,2176.18
PLIMIT: R11.2 U2.10 | length 981.3
  Top Layer w15: v4@4683.58,2480.79 U2.10
  Top Layer w20: v4(4680.12,2484.25) v4@4683.58,2480.79
  Bottom Layer w20: R11.2 4297.2,2319.84 4515.71,2319.84 v4(4680.12,2484.25)
PVCCL: C9.1 C10.2 C11.2 L3.1 U2.27 U2.28 | length 963.4
  Top Layer w60: L3.1 5000,3298.78 C9.1 4998.23,3294.02 C10.2 4998.23,2855.51 5000.21,2855.51 U2.28
PVCCR: C25.1 C26.2 C27.2 L6.1 U2.15 U2.16 | length 958.8
  Top Layer w60: U2.15@5001.1,2378.43 C27.2 4998.23,2242.64 C26.2 4998.86,2099.88 C25.1 4998.86,1432.8 L6.1@5007.13,1424.53
RINN: C24.2 U2.11 | length 189.4
  Top Layer w15: C24.2@4607.76,2455.2 U2.11
  Top Layer w20: C24.2 C24.2@4607.76,2455.2
RINP: C17.2 U2.12 | length 274.8
  Top Layer w15: 4717.01,2429.61 U2.12
  Top Layer w20: C17.2 4589.57,2302.17 4717.01,2429.61
VCC: C12.2 L3.2 L6.2 P1.1.1 P1.1.2 R7.2 U2.7 | length 1470.3
  Top Layer w15: 4685.51,2557.56 U2.7
  Top Layer w20: C12.2 4227.36,3034.45 4309.06,3034.45 4529.53,2813.98 4529.53,2556.1 4543.31,2542.32 4670.28,2542.32 4685.51,2557.56 ; R7.2 4733.55,3017.01 v2(4734.25,3017.72)
  Top Layer w40: C12.2 4226.38,3045.28 v2(4226.38,3134.84)
  Top Layer w80: L3.2@5201.54,3670.51 L3.2 5204.72,3675.63 v3(5204.72,3880.91) ; L6.2@5206.73,1424.53 5208.03,1423.23 v3(5352.36,1423.23)
pads on no net: J1.None U3.1 U3.4

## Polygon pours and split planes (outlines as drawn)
VCC on Internal Plane 2 (split plane): 7287.97,690.37 3030.1,690.37 3030.1,4718.09 7287.97,4718.09
GND on Internal Plane 1 (split plane): 7287.97,690.37 3030.1,690.37 3030.1,4718.09 7287.97,4718.09

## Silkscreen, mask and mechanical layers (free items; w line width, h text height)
Mechanical 1:
  the board outline again, w10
